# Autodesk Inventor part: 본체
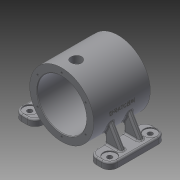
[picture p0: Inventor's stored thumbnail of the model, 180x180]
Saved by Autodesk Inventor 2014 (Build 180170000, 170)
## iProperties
Created: 2024-02
Part Number: 본체
Material: 알루미늄 6061
Document SubType Name: Modeling
Designer: mdu-01
Density: 2.71 g/cm^3
Appearance: 기본값
Mass: 1628.82 g
Surface Area: 1087.98 cm^2
Volume: 601.04 cm^3
Author: mdu-01
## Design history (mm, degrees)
sketch "스케치1"
  geometry: C1 r 12 at (0, 11) reference; C2 r 60 at (0, 11); C3 r 46 at (0, 11); C4 r 14 at (0, -20) reference; A1 r 16 centre (0, -20) between (-3.969, -4.5) and (3.969, -4.5) reference; 1 further point
  constraints: 2 centre point, 2 coincident
  dimensions: "d0" = 120 diameter of C2; "d1" = 14 radial gap between concentric circles of C2 C3
extrude "돌출1" new body sketch "스케치1" distance "d2" = 106; taper "d3" = 0 deg
sketch "스케치2"
  geometry: L1 (58, 89)-(67, 89) reference; L2 (71, 0)-(71, 106) reference; L3 (53, 94)-(53, 64) reference; L4 (53, 79)-(71, 79); L5 (67, 89)-(71, 89); L6 (53, 94)-(58, 94); L7 (58, 94)-(58, 89); L8 (53, 79)-(43, 79); L9 (43, 79)-(43, 94); L10 (43, 94)-(53, 94); 1 further point
  constraints: 16 end point, 4 perpendicular, 2 parallel, 2 point on line, 1 horizontal, 1 midpoint, 1 vertical, 2 other
  dimensions: "d5" = 10 distance between parallel lines of L9 L3
revolve "회전1" sketch "스케치2" stored, may be unused: angle "d4" = 90 deg
sketch "스케치3"
  geometry: C1 r 60 at (0, 0) reference; 2 further points
  constraints: 2 vertical alignment, 2 other
  dimensions: "d6" = 8 dimension on C1
hole "구멍1" sketch "스케치3" at (0, 52) diameter "d7" = 3.242; stored, may be unused: countersink angle "d11" = 90 deg, drill point angle "d13" = 118 deg; dims "d8" = 8, "d9" = 8, "d10" = 4.6, "d12" = 10
hole "구멍2" diameter "d16" = 3.242; stored, may be unused: countersink angle "d20" = 90 deg, drill point angle "d22" = 118 deg; dims "d14" = 10, "d15" = 10, "d17" = 8, "d18" = 8, "d19" = 4.6, "d21" = 10
sketch "스케치4"
  geometry: L1 (50, -54)-(90, -54); L2 (90, -54)-(90, -42); L3 (90, -42)-(50, -42); L4 (50, -42)-(50, -54); C1 r 60 at (0, 11) reference; 1 further point
  constraints: 8 end point, 2 parallel, 1 horizontal, 1 perpendicular
  dimensions: "d26" = 12 distance between parallel lines of L1 L3; "d28" = 65 distance from line of L1 C1.centre; "d29" = 50 distance from line of L4 C1.centre; "d30" = 40 distance between parallel lines of L2 L4
extrude "돌출2" join sketch "스케치4" distance "d31" = 106; taper "d32" = 0 deg
node "작업 평면1"
sketch "스케치5"
  geometry: L1 (-90, -42)-(-50, -42) reference; L2 (-50, -42)-(-50, -22.166); L3 (-80, -42)-(-58.084, -4.041); A1 r 60 centre (0, 11) between (-50, -22.166) and (-58.084, -4.041) reference; 1 further point
  constraints: 4 end point, 2 point on circle, 1 perpendicular, 1 point on line
  dimensions: "d33" = 10 distance of L3.start L1.start; "d34" = 60 deg angle of L1 L3
extrude "돌출3" join sketch "스케치5" distance "d37" = 9; taper "d38" = 0 deg
node "작업 평면3"
fillet "모깎기1" dims "d39" = 15
sketch "스케치6"
  geometry: A1 r 15 centre (25, 16) between (40, 16) and (25, 31) reference; A2 r 15 centre (25, -60) between (25, -75) and (40, -60) reference; 1 further point
hole "구멍3" sketch "스케치6" at (25, -60), (25, 16) diameter "d40" = 9; stored, may be unused: countersink angle "d44" = 90 deg, drill point angle "d46" = 118 deg; dims "d41" = 8, "d42" = 24, "d43" = 2, "d45" = 10
fillet "모깎기2" dims "d47" = 3
fillet "모깎기3" dims "d48" = 3
fillet "모깎기4" dims "d49" = 3
fillet "모깎기5" dims "d50" = 3
sketch "스케치7"
  geometry: L1 (71, 106)-(-49, 106) reference; 3 further points
  constraints: 1 midpoint, 1 vertical alignment, 1 other
  dimensions: "d51" = 53 distance from line of point (11, 53) L1
feature "엠보싱1" sketch "스케치7" dims "d0" = 120, "d1" = 14, "d52" = 0.5, "d53" = 0
chamfer "모따기1" distance "d54" = 1; stored, may be unused: second distance "d55" = 2, angle "d56" = 45 deg
node "솔리드1"
pattern_circular "원형 패턴1" dims angle "d24" = 360 deg
mirror "대칭1"
mirror "대칭2"
node "참조1"
node "참조2"
node "참조3"
node "참조4"
